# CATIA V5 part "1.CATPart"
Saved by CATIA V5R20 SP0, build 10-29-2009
Part number: 1
Bounding box of the stored display mesh (mm): x -100.012 to 94.068, y -100.02 to 99.993, z -0.901 to 40
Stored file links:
  E:\Ehsan\Amoozesh\CATIA\CATIA Course\Advanced\Videos\Session-21\1.CATPart
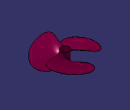
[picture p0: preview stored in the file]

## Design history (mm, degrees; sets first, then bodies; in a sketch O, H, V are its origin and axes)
Set1
  Extrude1: Lim1 40, Lim2 0, Element1 Sketch2
  Point1: type OnCurve, Support edge of Extrude1, RefPoint {extremum Reference edge of Extrude1, Direction (1, 2, 3)}, Length 14.465
  Line1: type PtDir, LineSecondUpto Sketch2, RefPoint Point1, Direction (0, 0, 1), Start 0, End 20
  CircPattern1: of Line1, instances 2, angular step 120, axis from face of Extrude1 from Sketch2.A1
  Line2: type PtPt, FirstPoint Point1, SecondPoint vertex of CircPattern1, Support Extrude1
  Sketch1 on xy-plane, origin (0, 0, 0), H (1, 0, 0), V (0, 1, 0)
    circle A1 centre (0, 0) radius 100
    radius A1 = 100
  Extrude2: Lim1 40, Lim2 0, Element1 Sketch1
  Project1: ToProject Line1, Support Extrude2
  Project2: ToProject Line2, Support Extrude2
  Project3: ToProject CircPattern1, Support Extrude2
  Line3: type PtPt, FirstPoint vertex of Project1, SecondPoint Point1
  Line4: type PtPt, FirstPoint vertex of CircPattern1, SecondPoint vertex of Project2
  Fill1: Boundary (Line4; Project2; Line3; Line2)
  Corner1: Element1 Line4, Element2 Project2, Support Fill1, Radius 40
  Corner2: Element1 Line3, Element2 Project2, Support Fill1, Radius 20
  Split1: ToCut Fill1, Cutting Corner1
  Split2: ToCut Split1, Cutting Corner2
  CircPattern2: of Split2, instances 3, angular step 120, axis from face of Extrude1 from Sketch2.A1
Body1 (main body)
  Sketch2 on xy-plane, origin (0, 0, 0), H (1, 0, 0), V (0, 1, 0)
    circle A1 centre (0, 0) radius 15
    radius A1 = 15
  ThickSurface1: Surface Split2, TopOffset 1, BotOffset 0
  ThickSurface2: Surface CircPattern2, TopOffset 1, BotOffset 0
  ThickSurface3: Surface Extrude1, TopOffset 1, BotOffset 1
  FaceFillet1: Radius 2, Face1 face of ThickSurface1, Face2 face of ThickSurface3, ConicRatio 0.5
  FaceFillet2: Radius 2, Face1 face of ThickSurface1, Face2 face of ThickSurface3, ConicRatio 0.5
  FaceFillet3: Radius 2, Face1 face of ThickSurface2, Face2 face of ThickSurface3, ConicRatio 0.5
  FaceFillet4: Radius 2, Face1 face of ThickSurface2, Face2 face of ThickSurface3, ConicRatio 0.5
  FaceFillet5: Radius 2, Face1 face of ThickSurface2, Face2 face of ThickSurface3, ConicRatio 0.5
  FaceFillet6: Radius 2, Face1 face of ThickSurface2, Face2 face of ThickSurface3, ConicRatio 0.5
